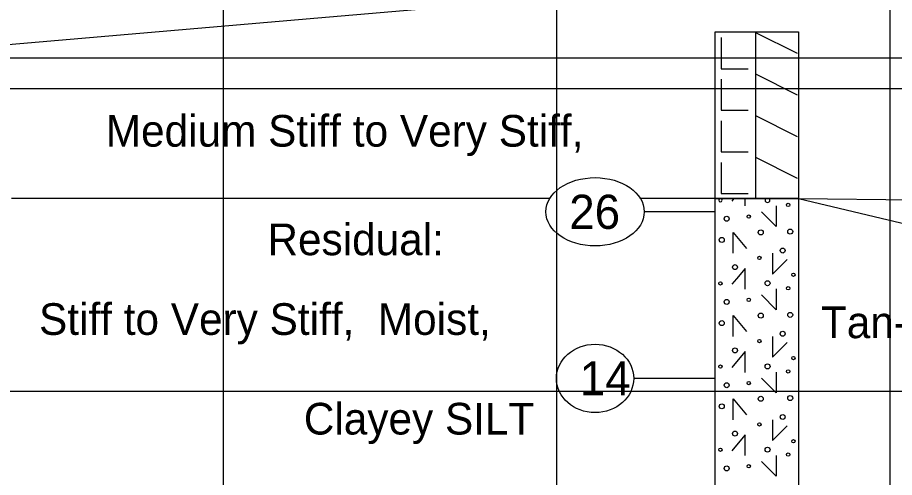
# Model space of a CAD drawing. Extents: x 278618 to 280654, y 171155 to 171855.
# Drawn here: x 280460.51 to 280486.82, y 171245.16 to 171258.96 of the extents above; entities that cross this region are included whole.
import ezdxf

# ---------------------------------------------------------------- set-up
doc = ezdxf.new("R2010")
doc.units = 0
for name, color, linetype in [('Exist XS Ground Line', 7, 'Continuous'), ('Old_Level_39', 7, 'Continuous'), ('Prop Road Sect_ Boring - Material (Outline)', 7, 'Continuous'), ('Prop Road Sect_ Boring - Peripheral (SPT Oval + Leader)', 7, 'Continuous'), ('Prop Road Sect_ Boring - Peripheral (SPT Tx)', 7, 'Continuous'), ('Prop Road Sect_ Material - Contact (General - Major)', 7, 'Continuous'), ('Prop Road Sect_ Material - Contact (General - Minor)', 7, 'Continuous'), ('Prop Road Sect_ Material - Tx (Composite Desc)', 7, 'Continuous'), ('Prop Strc Sect_ Grid - minor', 7, 'Continuous')]:
    doc.layers.add(name, color=color, linetype=linetype)

msp = doc.modelspace()

# ---------------------------------------------------------------- linework, layer by layer
at = {"layer": 'Exist XS Ground Line'}
msp.add_lwpolyline([(280458.478, 171258.006), (280469.522, 171258.957), (280479.922, 171259.853), (280483.411, 171260.153), (280487.772, 171260.528)], dxfattribs=at)
at = {"layer": 'Old_Level_39'}
msp.add_line((280456.689, 171256.833), (280506.689, 171256.833), dxfattribs=at)
at = {"layer": 'Prop Road Sect_ Boring - Material (Outline)'}
for p, q in [((280482.007, 171253.533), (280481.941, 171253.455)), ((280482.007, 171253.533), (280481.941, 171253.455)), ((280482.344, 171253.308), (280482.344, 171253.533)), ((280482.344, 171253.308), (280482.344, 171253.533)), ((280482.083, 171251.125), (280481.941, 171250.957)), ((280482.083, 171251.125), (280481.941, 171250.957)), ((280482.344, 171250.811), (280482.344, 171251.125)), ((280482.344, 171250.811), (280482.344, 171251.125)), ((280482.083, 171248.628), (280481.941, 171248.46)), ((280482.083, 171248.628), (280481.941, 171248.46)), ((280482.344, 171248.313), (280482.344, 171248.628)), ((280482.344, 171248.313), (280482.344, 171248.628)), ((280482.083, 171246.13), (280481.941, 171245.962)), ((280482.083, 171246.13), (280481.941, 171245.962)), ((280482.344, 171245.816), (280482.344, 171246.13)), ((280482.344, 171245.816), (280482.344, 171246.13))]:
    msp.add_line(p, q, dxfattribs=at)
for points in [[(280481.439, 171258.533), (280483.939, 171258.533), (280483.939, 171253.533), (280481.439, 171253.533)], [(280481.439, 171253.533), (280483.939, 171253.533), (280483.939, 171243.633), (280481.439, 171243.633)]]:
    msp.add_lwpolyline(points, close=True, dxfattribs=at)
for points in [[(280483.273, 171253.317), (280483.273, 171252.692), (280482.83, 171253.135)], [(280483.273, 171253.317), (280483.273, 171252.692), (280482.83, 171253.135)], [(280481.978, 171251.888), (280481.978, 171252.513), (280482.38, 171252.035)], [(280481.978, 171251.888), (280481.978, 171252.513), (280482.38, 171252.035)], [(280483.16, 171251.888), (280483.16, 171251.263), (280483.603, 171251.706)], [(280483.16, 171251.888), (280483.16, 171251.263), (280483.603, 171251.706)], [(280482.344, 171251.125), (280482.344, 171251.436), (280482.083, 171251.125)], [(280482.344, 171251.125), (280482.344, 171251.436), (280482.083, 171251.125)], [(280483.273, 171250.82), (280483.273, 171250.195), (280482.83, 171250.637)], [(280483.273, 171250.82), (280483.273, 171250.195), (280482.83, 171250.637)], [(280481.978, 171249.391), (280481.978, 171250.016), (280482.38, 171249.537)], [(280481.978, 171249.391), (280481.978, 171250.016), (280482.38, 171249.537)], [(280483.16, 171249.391), (280483.16, 171248.766), (280483.603, 171249.208)], [(280483.16, 171249.391), (280483.16, 171248.766), (280483.603, 171249.208)], [(280482.344, 171248.628), (280482.344, 171248.938), (280482.083, 171248.628)], [(280482.344, 171248.628), (280482.344, 171248.938), (280482.083, 171248.628)], [(280483.273, 171248.322), (280483.273, 171247.697), (280482.83, 171248.14)], [(280483.273, 171248.322), (280483.273, 171247.697), (280482.83, 171248.14)], [(280481.978, 171246.893), (280481.978, 171247.518), (280482.38, 171247.04)], [(280481.978, 171246.893), (280481.978, 171247.518), (280482.38, 171247.04)], [(280483.16, 171246.893), (280483.16, 171246.268), (280483.603, 171246.711)], [(280483.16, 171246.893), (280483.16, 171246.268), (280483.603, 171246.711)], [(280482.344, 171246.13), (280482.344, 171246.441), (280482.083, 171246.13)], [(280482.344, 171246.13), (280482.344, 171246.441), (280482.083, 171246.13)], [(280483.273, 171245.824), (280483.273, 171245.199), (280482.83, 171245.642)], [(280483.273, 171245.824), (280483.273, 171245.199), (280482.83, 171245.642)]]:
    msp.add_lwpolyline(points, dxfattribs=at)
for centre, radius in [((280483.633, 171253.338), 0.05), ((280483.633, 171253.338), 0.05), ((280481.788, 171252.924), 0.075), ((280481.788, 171252.924), 0.075), ((280482.452, 171252.988), 0.05), ((280482.452, 171252.988), 0.05), ((280482.809, 171252.515), 0.075), ((280482.809, 171252.515), 0.075), ((280483.694, 171252.538), 0.075), ((280483.694, 171252.538), 0.075), ((280481.64, 171252.289), 0.075), ((280481.64, 171252.289), 0.075), ((280483.468, 171251.97), 0.075), ((280483.468, 171251.97), 0.075), ((280482.77, 171251.749), 0.05), ((280482.77, 171251.749), 0.05), ((280482.038, 171251.472), 0.075), ((280482.038, 171251.472), 0.075), ((280483.788, 171251.242), 0.05), ((280483.788, 171251.242), 0.05), ((280481.601, 171250.986), 0.05), ((280481.601, 171250.986), 0.05), ((280483.013, 171250.99), 0.075), ((280483.013, 171250.99), 0.075), ((280483.633, 171250.84), 0.05), ((280483.633, 171250.84), 0.05), ((280481.788, 171250.427), 0.075), ((280481.788, 171250.427), 0.075), ((280482.452, 171250.491), 0.05), ((280482.452, 171250.491), 0.05), ((280482.809, 171250.018), 0.075), ((280482.809, 171250.018), 0.075), ((280483.694, 171250.04), 0.075), ((280483.694, 171250.04), 0.075), ((280481.64, 171249.792), 0.075), ((280481.64, 171249.792), 0.075), ((280483.468, 171249.473), 0.075), ((280483.468, 171249.473), 0.075), ((280482.77, 171249.252), 0.05), ((280482.77, 171249.252), 0.05), ((280482.038, 171248.974), 0.075), ((280482.038, 171248.974), 0.075), ((280483.788, 171248.745), 0.05), ((280483.788, 171248.745), 0.05), ((280481.601, 171248.489), 0.05), ((280481.601, 171248.489), 0.05), ((280483.013, 171248.493), 0.075), ((280483.013, 171248.493), 0.075), ((280483.633, 171248.343), 0.05), ((280483.633, 171248.343), 0.05), ((280481.788, 171247.929), 0.075), ((280481.788, 171247.929), 0.075), ((280482.452, 171247.993), 0.05), ((280482.452, 171247.993), 0.05), ((280482.809, 171247.52), 0.075), ((280482.809, 171247.52), 0.075), ((280483.694, 171247.543), 0.075), ((280483.694, 171247.543), 0.075), ((280481.64, 171247.294), 0.075), ((280481.64, 171247.294), 0.075), ((280483.468, 171246.975), 0.075), ((280483.468, 171246.975), 0.075), ((280482.77, 171246.754), 0.05), ((280482.77, 171246.754), 0.05), ((280482.038, 171246.477), 0.075), ((280482.038, 171246.477), 0.075), ((280483.788, 171246.247), 0.05), ((280483.788, 171246.247), 0.05), ((280481.601, 171245.991), 0.05), ((280481.601, 171245.991), 0.05), ((280483.013, 171245.995), 0.075), ((280483.013, 171245.995), 0.075), ((280483.633, 171245.845), 0.05), ((280483.633, 171245.845), 0.05), ((280481.788, 171245.432), 0.075), ((280481.788, 171245.432), 0.075), ((280482.452, 171245.496), 0.05), ((280482.452, 171245.496), 0.05)]:
    msp.add_circle(centre, radius, dxfattribs=at)
for centre, radius, start, end in [((280481.601, 171253.484), 0.05, 101.4052, 78.5948), ((280481.601, 171253.484), 0.05, 101.4052, 78.5948), ((280483.013, 171253.488), 0.075, 143.1268, 36.8732), ((280483.013, 171253.488), 0.075, 143.1268, 36.8732)]:
    msp.add_arc(centre, radius, start, end, dxfattribs=at)
at = {"layer": 'Prop Road Sect_ Boring - Peripheral (SPT Oval + Leader)'}
for p, q in [((280481.439, 171253.133), (280479.314, 171253.133)), ((280481.439, 171248.133), (280478.999, 171248.133))]:
    msp.add_line(p, q, dxfattribs=at)
for centre, major_axis, ratio in [((280477.839, 171253.133), (1.475, 0), 0.695008), ((280477.839, 171248.133), (1.16, 0), 0.883591)]:
    msp.add_ellipse(centre, major_axis=major_axis, ratio=ratio, dxfattribs=at)
at = {"layer": 'Prop Road Sect_ Material - Contact (General - Major)'}
for p, q in [((280476.483, 171253.533), (280460.325, 171253.533)), ((280481.439, 171253.533), (280479.181, 171253.533)), ((280483.939, 171253.533), (280520.951, 171253.087))]:
    msp.add_line(p, q, dxfattribs=at)
at = {"layer": 'Prop Road Sect_ Material - Contact (General - Minor)'}
msp.add_line((280483.939, 171253.533), (280525.439, 171243.633), dxfattribs=at)
at = {"layer": 'Prop Road Sect_ Material - Tx (Composite Desc)'}
for p, q in [((280481.619, 171258.359), (280481.619, 171257.427)), ((280481.619, 171258.359), (280481.619, 171257.427)), ((280482.65, 171258.533), (280482.65, 171258.518)), ((280482.65, 171258.533), (280482.65, 171258.518)), ((280482.65, 171258.518), (280482.65, 171256.02)), ((280482.65, 171258.518), (280483.899, 171257.893)), ((280482.65, 171258.518), (280482.65, 171256.02)), ((280482.65, 171258.518), (280483.899, 171257.893)), ((280481.619, 171257.427), (280482.432, 171257.427)), ((280481.619, 171257.427), (280482.432, 171257.427)), ((280482.65, 171257.269), (280483.899, 171256.644)), ((280482.65, 171257.269), (280483.899, 171256.644)), ((280481.619, 171257.11), (280481.619, 171256.179)), ((280481.619, 171257.11), (280481.619, 171256.179)), ((280481.619, 171256.179), (280482.432, 171256.179)), ((280481.619, 171256.179), (280482.432, 171256.179)), ((280482.65, 171256.02), (280482.65, 171253.533)), ((280482.65, 171256.02), (280483.899, 171255.396)), ((280482.65, 171256.02), (280482.65, 171253.533)), ((280482.65, 171256.02), (280483.899, 171255.396)), ((280481.619, 171255.861), (280481.619, 171254.93)), ((280481.619, 171255.861), (280481.619, 171254.93)), ((280481.619, 171254.93), (280482.432, 171254.93)), ((280481.619, 171254.93), (280482.432, 171254.93)), ((280482.65, 171254.771), (280483.899, 171254.147)), ((280482.65, 171254.771), (280483.899, 171254.147)), ((280481.619, 171254.613), (280481.619, 171253.681)), ((280481.619, 171254.613), (280481.619, 171253.681)), ((280481.619, 171253.681), (280482.432, 171253.681)), ((280481.619, 171253.681), (280482.432, 171253.681))]:
    msp.add_line(p, q, dxfattribs=at)
at = {"layer": 'Prop Strc Sect_ Grid - minor'}
for p, q in [((280466.689, 171188.859), (280466.689, 171293.859)), ((280476.689, 171188.859), (280476.689, 171293.859)), ((280486.689, 171188.859), (280486.689, 171293.859)), ((280586.689, 171257.743), (280436.689, 171257.743)), ((280586.689, 171247.743), (280436.689, 171247.743))]:
    msp.add_line(p, q, dxfattribs=at)

# ---------------------------------------------------------------- texts
at = {"layer": 'Prop Road Sect_ Boring - Peripheral (SPT Tx)'}
for s, p in [('26', (280477.065, 171252.62)), ('14', (280477.379, 171247.62))]:
    msp.add_text(s, height=1.025, dxfattribs=at).set_placement(p)
at = {"layer": 'Prop Road Sect_ Material - Tx (Composite Desc)'}
for s, p in [('Medium Stiff to Very Stiff,', (280463.158, 171255.089)), ('Residual:', (280468.008, 171251.831)), ('Stiff to Very Stiff,  Moist,', (280461.155, 171249.439)), ('Tan-Brown-Gray,', (280484.616, 171249.341)), ('Clayey SILT', (280469.1, 171246.449))]:
    msp.add_text(s, height=0.95, dxfattribs=at).set_placement(p)

doc.saveas('drawing.dxf')
